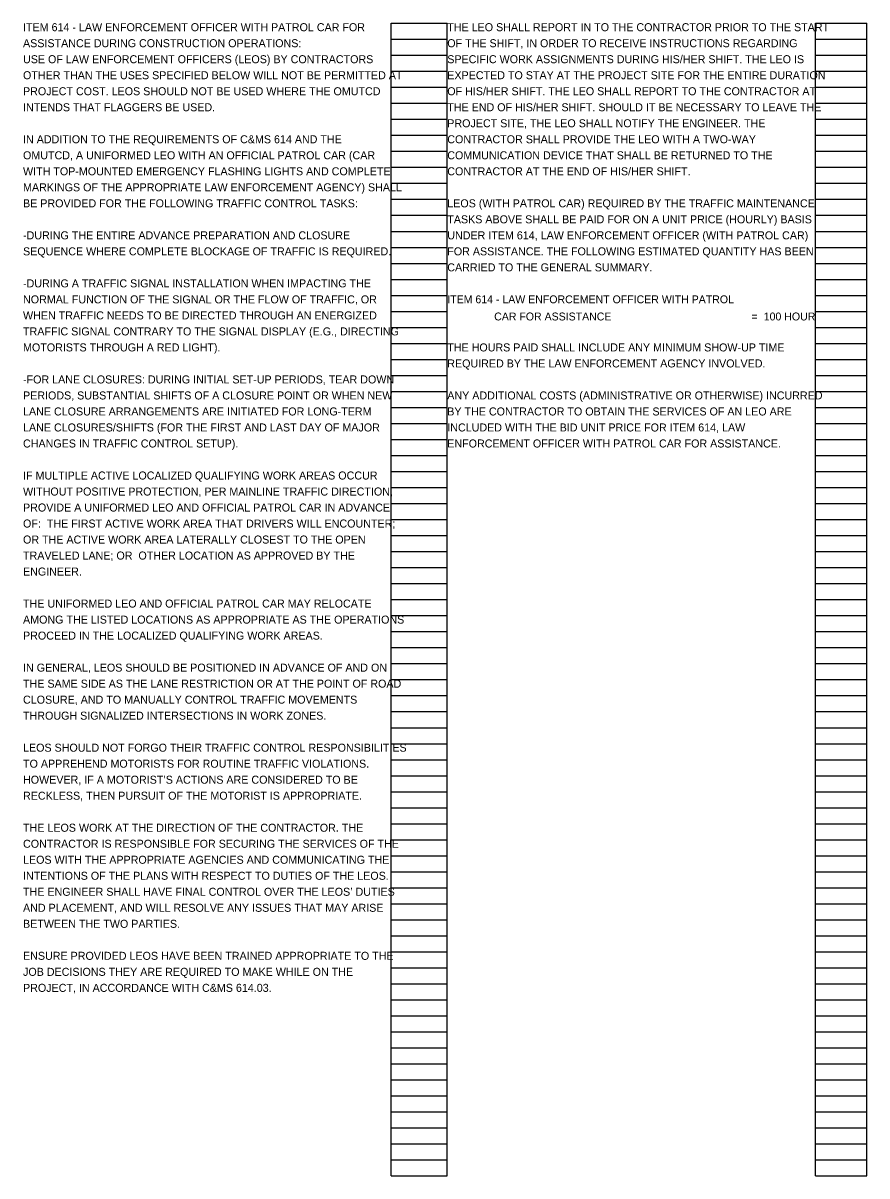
# Model space of a CAD drawing. Extents: x -23 to 32, y -58.1 to 21.1.
# Drawn here: x 17.24 to 32, y -28.09 to -7.93 of the extents above; entities that cross this region are included whole.
import ezdxf

# ---------------------------------------------------------------- set-up
doc = ezdxf.new("R2010")
doc.units = 0
for name, color, linetype in [('Default', 7, 'Continuous'), ('SH_Data', 7, 'Continuous'), ('SH_Text', 7, 'Continuous')]:
    doc.layers.add(name, color=color, linetype=linetype)

msp = doc.modelspace()

# ---------------------------------------------------------------- linework, layer by layer
at = {"layer": 'SH_Data'}
for p, q in [((23.68, -28.093), (23.68, -7.933)), ((23.68, -7.933), (24.66, -7.933)), ((24.66, -28.093), (24.66, -7.933)), ((31.1, -28.093), (31.1, -7.933)), ((31.1, -7.933), (32, -7.933)), ((32, -28.093), (32, -7.933)), ((23.68, -8.213), (24.66, -8.213)), ((31.1, -8.213), (32, -8.213)), ((23.68, -8.493), (24.66, -8.493)), ((31.1, -8.493), (32, -8.493)), ((23.68, -8.773), (24.66, -8.773)), ((31.1, -8.773), (32, -8.773)), ((23.68, -9.053), (24.66, -9.053)), ((31.1, -9.053), (32, -9.053)), ((23.68, -9.333), (24.66, -9.333)), ((31.1, -9.333), (32, -9.333)), ((23.68, -9.613), (24.66, -9.613)), ((31.1, -9.613), (32, -9.613)), ((23.68, -9.893), (24.66, -9.893)), ((31.1, -9.893), (32, -9.893)), ((23.68, -10.173), (24.66, -10.173)), ((31.1, -10.173), (32, -10.173)), ((23.68, -10.453), (24.66, -10.453)), ((31.1, -10.453), (32, -10.453)), ((23.68, -10.733), (24.66, -10.733)), ((31.1, -10.733), (32, -10.733)), ((23.68, -11.013), (24.66, -11.013)), ((31.1, -11.013), (32, -11.013)), ((23.68, -11.293), (24.66, -11.293)), ((31.1, -11.293), (32, -11.293)), ((23.68, -11.573), (24.66, -11.573)), ((31.1, -11.573), (32, -11.573)), ((23.68, -11.853), (24.66, -11.853)), ((31.1, -11.853), (32, -11.853)), ((23.68, -12.133), (24.66, -12.133)), ((31.1, -12.133), (32, -12.133)), ((23.68, -12.413), (24.66, -12.413)), ((31.1, -12.413), (32, -12.413)), ((23.68, -12.693), (24.66, -12.693)), ((31.1, -12.693), (32, -12.693)), ((23.68, -12.973), (24.66, -12.973)), ((31.1, -12.973), (32, -12.973)), ((23.68, -13.253), (24.66, -13.253)), ((31.1, -13.253), (32, -13.253)), ((23.68, -13.533), (24.66, -13.533)), ((31.1, -13.533), (32, -13.533)), ((23.68, -13.813), (24.66, -13.813)), ((31.1, -13.813), (32, -13.813)), ((23.68, -14.093), (24.66, -14.093)), ((31.1, -14.093), (32, -14.093)), ((23.68, -14.373), (24.66, -14.373)), ((31.1, -14.373), (32, -14.373)), ((23.68, -14.653), (24.66, -14.653)), ((31.1, -14.653), (32, -14.653)), ((23.68, -14.933), (24.66, -14.933)), ((31.1, -14.933), (32, -14.933)), ((23.68, -15.213), (24.66, -15.213)), ((31.1, -15.213), (32, -15.213)), ((23.68, -15.493), (24.66, -15.493)), ((31.1, -15.493), (32, -15.493)), ((23.68, -15.773), (24.66, -15.773)), ((31.1, -15.773), (32, -15.773)), ((23.68, -16.053), (24.66, -16.053)), ((31.1, -16.053), (32, -16.053)), ((23.68, -16.333), (24.66, -16.333)), ((31.1, -16.333), (32, -16.333)), ((23.68, -16.613), (24.66, -16.613)), ((31.1, -16.613), (32, -16.613)), ((23.68, -16.893), (24.66, -16.893)), ((31.1, -16.893), (32, -16.893)), ((23.68, -17.173), (24.66, -17.173)), ((31.1, -17.173), (32, -17.173)), ((23.68, -17.453), (24.66, -17.453)), ((31.1, -17.453), (32, -17.453)), ((23.68, -17.733), (24.66, -17.733)), ((31.1, -17.733), (32, -17.733)), ((23.68, -18.013), (24.66, -18.013)), ((31.1, -18.013), (32, -18.013)), ((23.68, -18.293), (24.66, -18.293)), ((31.1, -18.293), (32, -18.293)), ((23.68, -18.573), (24.66, -18.573)), ((31.1, -18.573), (32, -18.573)), ((23.68, -18.853), (24.66, -18.853)), ((31.1, -18.853), (32, -18.853)), ((23.68, -19.133), (24.66, -19.133)), ((31.1, -19.133), (32, -19.133)), ((23.68, -19.413), (24.66, -19.413)), ((31.1, -19.413), (32, -19.413)), ((23.68, -19.693), (24.66, -19.693)), ((31.1, -19.693), (32, -19.693)), ((23.68, -19.973), (24.66, -19.973)), ((31.1, -19.973), (32, -19.973)), ((23.68, -20.253), (24.66, -20.253)), ((31.1, -20.253), (32, -20.253)), ((23.68, -20.533), (24.66, -20.533)), ((31.1, -20.533), (32, -20.533)), ((23.68, -20.813), (24.66, -20.813)), ((31.1, -20.813), (32, -20.813)), ((23.68, -21.093), (24.66, -21.093)), ((31.1, -21.093), (32, -21.093)), ((23.68, -21.373), (24.66, -21.373)), ((31.1, -21.373), (32, -21.373)), ((23.68, -21.653), (24.66, -21.653)), ((31.1, -21.653), (32, -21.653)), ((23.68, -21.933), (24.66, -21.933)), ((31.1, -21.933), (32, -21.933)), ((23.68, -22.213), (24.66, -22.213)), ((31.1, -22.213), (32, -22.213)), ((23.68, -22.493), (24.66, -22.493)), ((31.1, -22.493), (32, -22.493)), ((23.68, -22.773), (24.66, -22.773)), ((31.1, -22.773), (32, -22.773)), ((23.68, -23.053), (24.66, -23.053)), ((31.1, -23.053), (32, -23.053)), ((23.68, -23.333), (24.66, -23.333)), ((31.1, -23.333), (32, -23.333)), ((23.68, -23.613), (24.66, -23.613)), ((31.1, -23.613), (32, -23.613)), ((23.68, -23.893), (24.66, -23.893)), ((31.1, -23.893), (32, -23.893)), ((23.68, -24.173), (24.66, -24.173)), ((31.1, -24.173), (32, -24.173)), ((23.68, -24.453), (24.66, -24.453)), ((31.1, -24.453), (32, -24.453)), ((23.68, -24.733), (24.66, -24.733)), ((31.1, -24.733), (32, -24.733)), ((23.68, -25.013), (24.66, -25.013)), ((31.1, -25.013), (32, -25.013)), ((23.68, -25.293), (24.66, -25.293)), ((31.1, -25.293), (32, -25.293)), ((23.68, -25.573), (24.66, -25.573)), ((31.1, -25.573), (32, -25.573)), ((23.68, -25.853), (24.66, -25.853)), ((31.1, -25.853), (32, -25.853)), ((23.68, -26.133), (24.66, -26.133)), ((31.1, -26.133), (32, -26.133)), ((23.68, -26.413), (24.66, -26.413)), ((31.1, -26.413), (32, -26.413)), ((23.68, -26.693), (24.66, -26.693)), ((31.1, -26.693), (32, -26.693)), ((23.68, -26.973), (24.66, -26.973)), ((31.1, -26.973), (32, -26.973)), ((23.68, -27.253), (24.66, -27.253)), ((31.1, -27.253), (32, -27.253)), ((23.68, -27.533), (24.66, -27.533)), ((31.1, -27.533), (32, -27.533)), ((23.68, -27.813), (24.66, -27.813)), ((31.1, -27.813), (32, -27.813)), ((23.68, -28.093), (24.66, -28.093)), ((31.1, -28.093), (32, -28.093))]:
    msp.add_line(p, q, dxfattribs=at)

# ---------------------------------------------------------------- texts
at = {"layer": 'Default'}
for s, p in [('ITEM 614 - LAW ENFORCEMENT OFFICER WITH PATROL', (24.66, -12.831)), ('                CAR FOR ASSISTANCE', (24.66, -13.131)), ('=', (29.981, -13.131)), ('100 HOUR', (30.195, -13.131))]:
    msp.add_text(s, height=0.138, dxfattribs=at).set_placement(p)
at = {"layer": 'SH_Text'}
for s, p in [('ITEM 614 - LAW ENFORCEMENT OFFICER WITH PATROL CAR FOR ', (17.24, -8.073)), ('THE LEO SHALL REPORT IN TO THE CONTRACTOR PRIOR TO THE START ', (24.66, -8.073)), ('ASSISTANCE DURING CONSTRUCTION OPERATIONS:', (17.24, -8.353)), ('OF THE SHIFT, IN ORDER TO RECEIVE INSTRUCTIONS REGARDING ', (24.66, -8.353)), ('USE OF LAW ENFORCEMENT OFFICERS (LEOS) BY CONTRACTORS ', (17.24, -8.633)), ('SPECIFIC WORK ASSIGNMENTS DURING HIS/HER SHIFT. THE LEO IS ', (24.66, -8.633)), ('OTHER THAN THE USES SPECIFIED BELOW WILL NOT BE PERMITTED AT ', (17.24, -8.913)), ('EXPECTED TO STAY AT THE PROJECT SITE FOR THE ENTIRE DURATION ', (24.66, -8.913)), ('PROJECT COST. LEOS SHOULD NOT BE USED WHERE THE OMUTCD ', (17.24, -9.193)), ('OF HIS/HER SHIFT. THE LEO SHALL REPORT TO THE CONTRACTOR AT ', (24.66, -9.193)), ('INTENDS THAT FLAGGERS BE USED.', (17.24, -9.473)), ('THE END OF HIS/HER SHIFT. SHOULD IT BE NECESSARY TO LEAVE THE ', (24.66, -9.473)), ('PROJECT SITE, THE LEO SHALL NOTIFY THE ENGINEER. THE ', (24.66, -9.753)), ('IN ADDITION TO THE REQUIREMENTS OF C&MS 614 AND THE ', (17.24, -10.033)), ('CONTRACTOR SHALL PROVIDE THE LEO WITH A TWO-WAY ', (24.66, -10.033)), ('OMUTCD, A UNIFORMED LEO WITH AN OFFICIAL PATROL CAR (CAR ', (17.24, -10.313)), ('COMMUNICATION DEVICE THAT SHALL BE RETURNED TO THE ', (24.66, -10.313)), ('WITH TOP-MOUNTED EMERGENCY FLASHING LIGHTS AND COMPLETE ', (17.24, -10.593)), ('CONTRACTOR AT THE END OF HIS/HER SHIFT.', (24.66, -10.593)), ('MARKINGS OF THE APPROPRIATE LAW ENFORCEMENT AGENCY) SHALL ', (17.24, -10.873)), ('BE PROVIDED FOR THE FOLLOWING TRAFFIC CONTROL TASKS:', (17.24, -11.153)), ('LEOS (WITH PATROL CAR) REQUIRED BY THE TRAFFIC MAINTENANCE ', (24.66, -11.153)), ('TASKS ABOVE SHALL BE PAID FOR ON A UNIT PRICE (HOURLY) BASIS ', (24.66, -11.433)), ('-DURING THE ENTIRE ADVANCE PREPARATION AND CLOSURE ', (17.24, -11.713)), ('UNDER ITEM 614, LAW ENFORCEMENT OFFICER (WITH PATROL CAR) ', (24.66, -11.713)), ('SEQUENCE WHERE COMPLETE BLOCKAGE OF TRAFFIC IS REQUIRED. ', (17.24, -11.993)), ('FOR ASSISTANCE. THE FOLLOWING ESTIMATED QUANTITY HAS BEEN ', (24.66, -11.993)), ('CARRIED TO THE GENERAL SUMMARY.', (24.66, -12.273)), ('-DURING A TRAFFIC SIGNAL INSTALLATION WHEN IMPACTING THE ', (17.24, -12.553)), ('NORMAL FUNCTION OF THE SIGNAL OR THE FLOW OF TRAFFIC, OR ', (17.24, -12.833)), ('WHEN TRAFFIC NEEDS TO BE DIRECTED THROUGH AN ENERGIZED ', (17.24, -13.113)), ('TRAFFIC SIGNAL CONTRARY TO THE SIGNAL DISPLAY (E.G., DIRECTING ', (17.24, -13.393)), ('MOTORISTS THROUGH A RED LIGHT). ', (17.24, -13.673)), ('THE HOURS PAID SHALL INCLUDE ANY MINIMUM SHOW-UP TIME ', (24.66, -13.673)), ('REQUIRED BY THE LAW ENFORCEMENT AGENCY INVOLVED. ', (24.66, -13.953)), ('-FOR LANE CLOSURES: DURING INITIAL SET-UP PERIODS, TEAR DOWN ', (17.24, -14.233)), ('PERIODS, SUBSTANTIAL SHIFTS OF A CLOSURE POINT OR WHEN NEW ', (17.24, -14.513)), ('ANY ADDITIONAL COSTS (ADMINISTRATIVE OR OTHERWISE) INCURRED ', (24.66, -14.513)), ('LANE CLOSURE ARRANGEMENTS ARE INITIATED FOR LONG-TERM ', (17.24, -14.793)), ('BY THE CONTRACTOR TO OBTAIN THE SERVICES OF AN LEO ARE ', (24.66, -14.793)), ('LANE CLOSURES/SHIFTS (FOR THE FIRST AND LAST DAY OF MAJOR ', (17.24, -15.073)), ('INCLUDED WITH THE BID UNIT PRICE FOR ITEM 614, LAW ', (24.66, -15.073)), ('CHANGES IN TRAFFIC CONTROL SETUP).', (17.24, -15.353)), ('ENFORCEMENT OFFICER WITH PATROL CAR FOR ASSISTANCE.', (24.66, -15.353)), ('IF MULTIPLE ACTIVE LOCALIZED QUALIFYING WORK AREAS OCCUR ', (17.24, -15.913)), ('WITHOUT POSITIVE PROTECTION, PER MAINLINE TRAFFIC DIRECTION, ', (17.24, -16.193)), ('PROVIDE A UNIFORMED LEO AND OFFICIAL PATROL CAR IN ADVANCE ', (17.24, -16.473)), ('OF:  THE FIRST ACTIVE WORK AREA THAT DRIVERS WILL ENCOUNTER; ', (17.24, -16.753)), ('OR THE ACTIVE WORK AREA LATERALLY CLOSEST TO THE OPEN ', (17.24, -17.033)), ('TRAVELED LANE; OR  OTHER LOCATION AS APPROVED BY THE ', (17.24, -17.313)), ('ENGINEER.', (17.24, -17.593)), ('THE UNIFORMED LEO AND OFFICIAL PATROL CAR MAY RELOCATE ', (17.24, -18.153)), ('AMONG THE LISTED LOCATIONS AS APPROPRIATE AS THE OPERATIONS ', (17.24, -18.433)), ('PROCEED IN THE LOCALIZED QUALIFYING WORK AREAS.', (17.24, -18.713)), ('IN GENERAL, LEOS SHOULD BE POSITIONED IN ADVANCE OF AND ON ', (17.24, -19.273)), ('THE SAME SIDE AS THE LANE RESTRICTION OR AT THE POINT OF ROAD ', (17.24, -19.553)), ('CLOSURE, AND TO MANUALLY CONTROL TRAFFIC MOVEMENTS ', (17.24, -19.833)), ('THROUGH SIGNALIZED INTERSECTIONS IN WORK ZONES. ', (17.24, -20.113)), ('LEOS SHOULD NOT FORGO THEIR TRAFFIC CONTROL RESPONSIBILITIES ', (17.24, -20.673)), ('TO APPREHEND MOTORISTS FOR ROUTINE TRAFFIC VIOLATIONS. ', (17.24, -20.953)), ('HOWEVER, IF A MOTORIST’S ACTIONS ARE CONSIDERED TO BE ', (17.24, -21.233)), ('RECKLESS, THEN PURSUIT OF THE MOTORIST IS APPROPRIATE. ', (17.24, -21.513)), ('THE LEOS WORK AT THE DIRECTION OF THE CONTRACTOR. THE ', (17.24, -22.073)), ('CONTRACTOR IS RESPONSIBLE FOR SECURING THE SERVICES OF THE ', (17.24, -22.353)), ('LEOS WITH THE APPROPRIATE AGENCIES AND COMMUNICATING THE ', (17.24, -22.633)), ('INTENTIONS OF THE PLANS WITH RESPECT TO DUTIES OF THE LEOS. ', (17.24, -22.913)), ('THE ENGINEER SHALL HAVE FINAL CONTROL OVER THE LEOS’ DUTIES ', (17.24, -23.193)), ('AND PLACEMENT, AND WILL RESOLVE ANY ISSUES THAT MAY ARISE ', (17.24, -23.473)), ('BETWEEN THE TWO PARTIES. ', (17.24, -23.753)), ('ENSURE PROVIDED LEOS HAVE BEEN TRAINED APPROPRIATE TO THE ', (17.24, -24.313)), ('JOB DECISIONS THEY ARE REQUIRED TO MAKE WHILE ON THE ', (17.24, -24.593)), ('PROJECT, IN ACCORDANCE WITH C&MS 614.03. ', (17.24, -24.873))]:
    msp.add_text(s, height=0.14, dxfattribs=at).set_placement(p)

doc.saveas('drawing.dxf')
